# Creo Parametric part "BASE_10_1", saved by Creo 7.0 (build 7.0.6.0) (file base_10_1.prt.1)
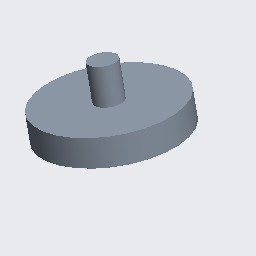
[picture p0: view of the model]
Units: millimeter Newton Second (mmNs); MM, TONNE, SECS

Created from: XX_MMNS_PART_SOLID_ABS.PRT

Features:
  1. datum plane "RIGHT"
  2. datum plane "TOP"
  3. datum plane "FRONT"
  4. coordinate system
  5. extrusion "Extrude 1"
  6. extrusion "Extrude 2"

Surfaces: 3 plane, 2 cylinder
